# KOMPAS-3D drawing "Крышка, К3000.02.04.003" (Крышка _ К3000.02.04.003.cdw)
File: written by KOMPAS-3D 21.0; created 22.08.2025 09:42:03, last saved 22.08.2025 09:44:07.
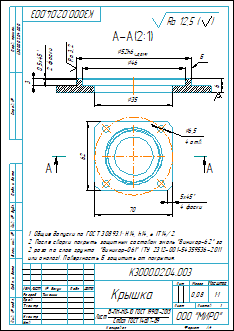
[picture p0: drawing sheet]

Sheet 1: A4, portrait

Document properties: Автор: Lutik; Полное имя файла: C:\Users\Lutik\YandexDisk\Документы\Новая папка\Бабка задняя\2D\Подшипниковый узел_К3000.02.04.000\Крышка _ К3000.02.04.003.cdw; Знак неуказанной шероховатости: 4; Параметр неуказанной шероховатости: Ra 12,5; Масса: 0.08479

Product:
- Part/product: Крышка  | designation К3000.02.04.003
    Материал: Лист$dБ-ПН-НО-10 ГОСТ 19903-2015;Ст3сп ГОСТ 14637-89$ (density 7850 kg/m3)
    Масса: 0.08479

Title block, sheet 1: Наименование: Крышка; designation: К3000.02.04.003; Материал: Лист Б-ПН-НО-10 ГОСТ 19903-2015 Ст3сп ГОСТ 14637-89; Масса: 0,08; Количество листов документа: 1; organisation: ООО "МИРО"; Форматы листов документа: A4; Разработал: Тимонин

Views: Вид 1, Слева, Разрез 2, Разрез А-А
Referenced files in C:\Users\Lutik\YandexDisk\Документы\Новая папка\Бабка задняя\3D\: Крышка_41.m3d
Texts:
  Ra 3,2
  Ra 12,5
  Ra 12,5 ( )
  К3000.02.04.003 Крышка
Dimensions and other numbers on the sheet: 70; 62; 5; 4 фаски; 6,5; 4 отв.; 52; 46; 6; 3; 0,5; 2 фаски; 35; 1:1; 1; 0,08

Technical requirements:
  Общие допуски по ГОСТ 30893.1: Н14, h14, ± IT14/2.
  После сварки покрыть защитным составом эмаль "Виникор-62" за
  2 раза по слою грунта  "Виникор-061" (ТУ 2312-001-54359536-2011
  или аналог). Поверхность Б защитить от покрытия.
